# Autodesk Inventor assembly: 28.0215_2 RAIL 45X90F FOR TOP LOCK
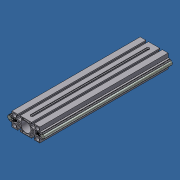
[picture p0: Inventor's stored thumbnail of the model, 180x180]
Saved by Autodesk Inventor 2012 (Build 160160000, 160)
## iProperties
Created: 2011-05
Part Number: 28.0215_2 RAIL 45X90F FOR TOP LOCK
Document SubType Name: Assembly
Designer: Administrator
Description: Rail 45x90 F For ADJ UNITS
Author: Administrator
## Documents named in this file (4)
- C:\Andys Backup Data\ANDY'S INVENTOR\INVENTOR LIBRARIES\PARTS LIBRARY\READY FOR USE MODULES LG\SUBCOMPONENTS\28.0215_2 RAIL 45X90F FOR TOP LOCK.iam
- C:\Andys Backup Data\ANDY'S INVENTOR\INVENTOR LIBRARIES\PARTS LIBRARY\READY FOR USE MODULES LG\SUBCOMPONENTS\28.0215_3 45x90F  PROFILE FOR TOP LOCK.ipt
- C:\Andys Backup Data\ANDY'S INVENTOR\INVENTOR LIBRARIES\PARTS LIBRARY\READY FOR USE MODULES LG\SUBCOMPONENTS\28.0215_7 SHAFT SUPP PROF TOP LOCK.ipt
- C:\Andys Backup Data\ANDY'S INVENTOR\INVENTOR LIBRARIES\PARTS LIBRARY\READY FOR USE MODULES LG\SUBCOMPONENTS\28.0215_6 SHAFT 12 FOR TOP LOCK.ipt
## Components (5 placed, 3 different names)
1. 28.0215_3 45x90F  PROFILE FOR TOP LOCK:1 — Mate:3, Mate:4, Mate:5, Mate:6, Mate:7, Mate:8
2. 28.0215_6 SHAFT 12 FOR TOP LOCK:1 — Mate:2, Flush:3, Mate:4
3. 28.0215_6 SHAFT 12 FOR TOP LOCK:2 — Mate:1, Flush:2, Mate:6
4. 28.0215_7 SHAFT SUPP PROF TOP LOCK:1 — Mate:1, Flush:2, Mate:5, Mate:7
5. 28.0215_7 SHAFT SUPP PROF TOP LOCK:2 — Mate:2, Flush:3, Mate:3, Mate:8
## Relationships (10: Mate 8, Flush 2)
- Mate:1: 28.0215_6 SHAFT 12 FOR TOP LOCK:2 ↔ 28.0215_7 SHAFT SUPP PROF TOP LOCK:1
- Flush:2: 28.0215_6 SHAFT 12 FOR TOP LOCK:2 ↔ 28.0215_7 SHAFT SUPP PROF TOP LOCK:1
- Mate:2: 28.0215_6 SHAFT 12 FOR TOP LOCK:1 ↔ 28.0215_7 SHAFT SUPP PROF TOP LOCK:2
- Flush:3: 28.0215_6 SHAFT 12 FOR TOP LOCK:1 ↔ 28.0215_7 SHAFT SUPP PROF TOP LOCK:2
- Mate:3: 28.0215_3 45x90F  PROFILE FOR TOP LOCK:1 ↔ 28.0215_7 SHAFT SUPP PROF TOP LOCK:2
- Mate:4: 28.0215_3 45x90F  PROFILE FOR TOP LOCK:1 ↔ 28.0215_6 SHAFT 12 FOR TOP LOCK:1
- Mate:5: 28.0215_3 45x90F  PROFILE FOR TOP LOCK:1 ↔ 28.0215_7 SHAFT SUPP PROF TOP LOCK:1
- Mate:6: 28.0215_3 45x90F  PROFILE FOR TOP LOCK:1 ↔ 28.0215_6 SHAFT 12 FOR TOP LOCK:2
- Mate:7: 28.0215_3 45x90F  PROFILE FOR TOP LOCK:1 ↔ 28.0215_7 SHAFT SUPP PROF TOP LOCK:1
- Mate:8: 28.0215_3 45x90F  PROFILE FOR TOP LOCK:1 ↔ 28.0215_7 SHAFT SUPP PROF TOP LOCK:2
